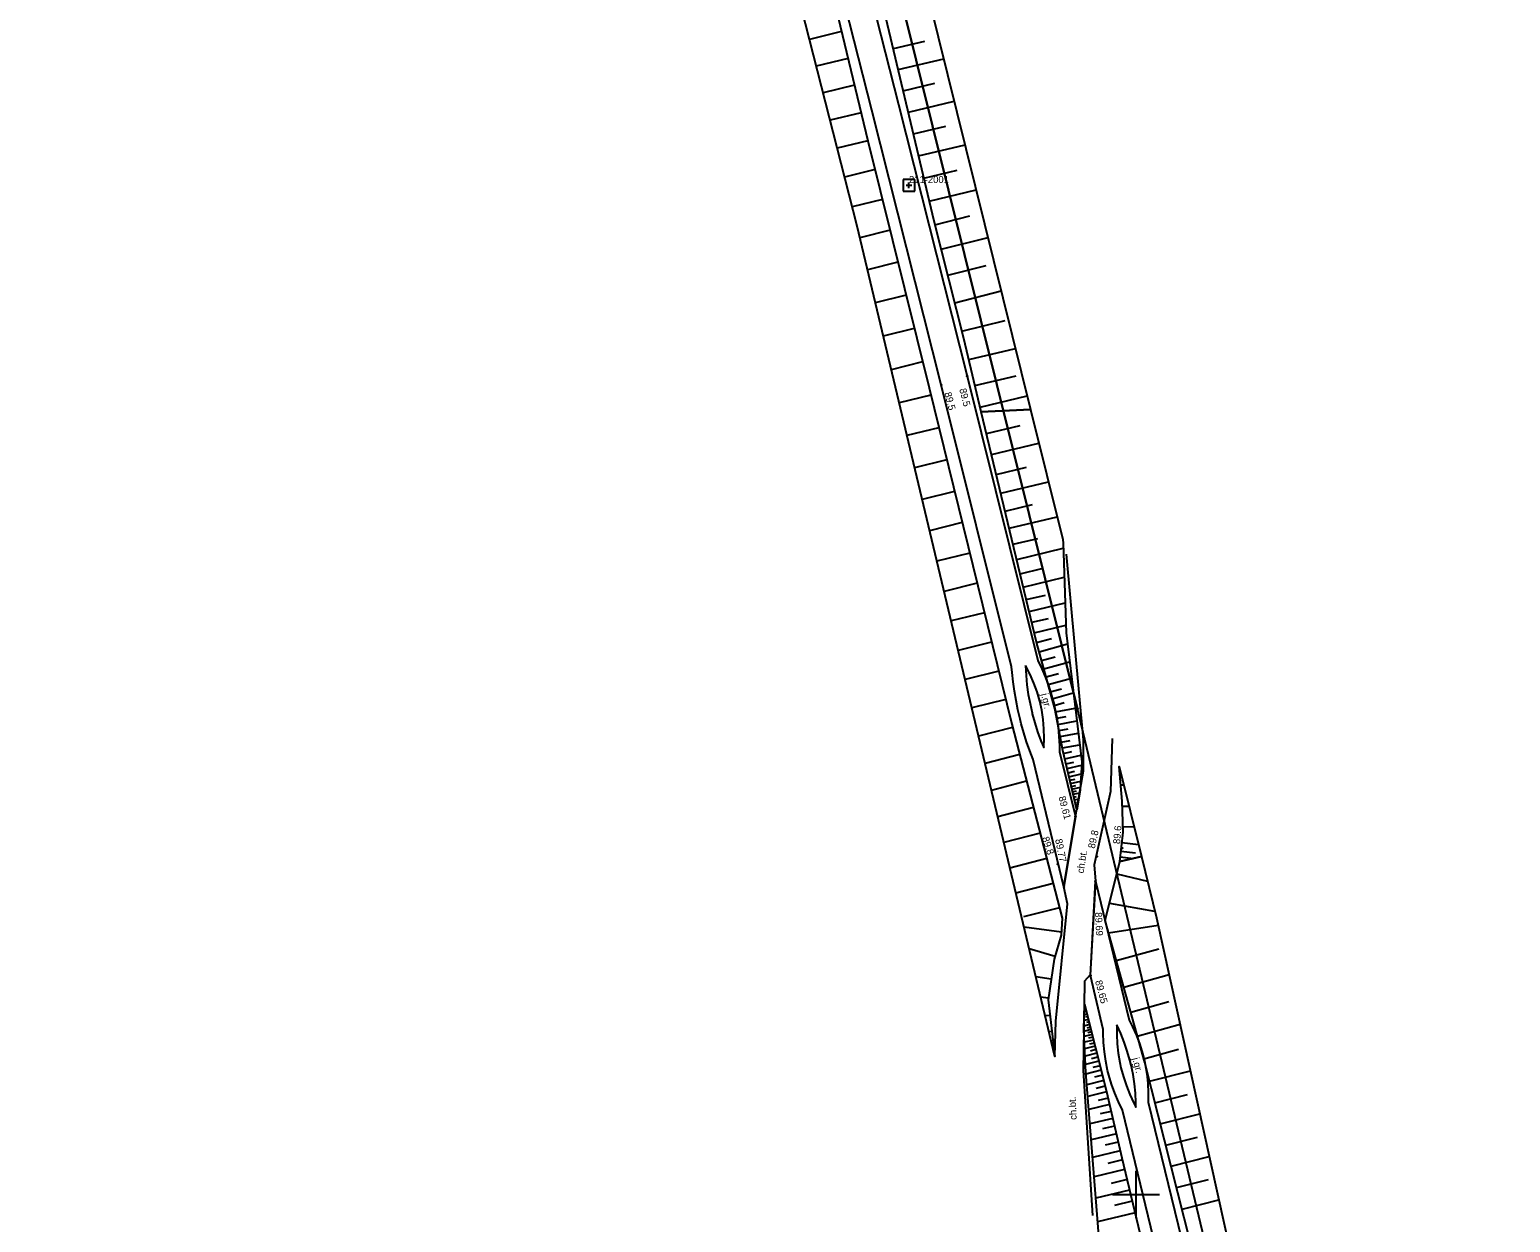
# Model space of a CAD drawing. Extents: x 7506075 to 7506993, y 5784375 to 5786367.
# Drawn here: x 7506732.7 to 7506889.7, y 5784747.1 to 5784873.4 of the extents above; entities that cross this region are included whole.
import ezdxf

# ---------------------------------------------------------------- set-up
doc = ezdxf.new("R2010")
doc.units = 0
for name, color, linetype in [('000 Inne (niezydentyfikowane)', 7, 'Continuous'), ('203-punkt graniczny', 7, 'Continuous'), ('216-obręb ewidencyjny', 7, 'Continuous'), ('218-kontur użytku gruntowego', 7, 'Continuous'), ('219-działka ewidencyjna', 7, 'Continuous'), ('chodnik', 7, 'Continuous'), ('chodnik-Atr17', 7, 'Continuous'), ('jezdnia', 7, 'Continuous'), ('jezdnia-Atr17', 7, 'Continuous'), ('pikieta naturalna', 7, 'Continuous'), ('pikieta naturalna-Atr2', 7, 'Continuous'), ('pikieta sztuczna', 7, 'Continuous'), ('pikieta sztuczna-Atr2', 7, 'Continuous'), ('skarpa nieumocniona', 7, 'Continuous'), ('skarpa umocniona', 7, 'Continuous'), ('Szczegółowa osnowa geodezyjna pozioma', 7, 'Continuous'), ('Szczegółowa osnowa geodezyjna pozioma-Atr103', 7, 'Continuous'), ('wał przeciwpowodziowy', 7, 'Continuous'), ('Wstawianie ramki sekcyjnej z opisem', 7, 'Continuous')]:
    doc.layers.add(name, color=color, linetype=linetype)

# ---------------------------------------------------------------- blocks, each defined once
blk = doc.blocks.new('PW01')
blk.add_circle((0, 0), 0.045)
blk = doc.blocks.new('203')
blk.add_circle((0, 0), 0.045)
blk = doc.blocks.new('OSSP')
for p, q in [((-0.626, 0.625), (-0.626, -0.625)), ((-0.626, 0.625), (-0.626, -0.625)), ((0.624, 0.625), (-0.626, 0.625)), ((0.624, 0.625), (-0.626, 0.625)), ((0.3, 0), (-0.3, 0)), ((0.3, 0), (-0.3, 0)), ((0, -0.3), (0, 0.3)), ((0, -0.3), (0, 0.3)), ((0.624, -0.625), (0.624, 0.625)), ((0.624, -0.625), (0.624, 0.625)), ((-0.626, -0.625), (0.624, -0.625)), ((-0.626, -0.625), (0.624, -0.625))]:
    blk.add_line(p, q)

msp = doc.modelspace()

# ---------------------------------------------------------------- linework, layer by layer
at = {"layer": '000 Inne (niezydentyfikowane)'}
for p, q in [((7506818.8, 5784873.2), (7506815.378, 5784872.379)), ((7506824.28, 5784871.4), (7506827.61, 5784872.19)), ((7506819.48, 5784870.36), (7506816.101, 5784869.55)), ((7506824.8, 5784869.18), (7506829.62, 5784870.323)), ((7506820.17, 5784867.51), (7506816.827, 5784866.705)), ((7506825.33, 5784866.94), (7506828.68, 5784867.73)), ((7506825.87, 5784864.67), (7506830.736, 5784865.818)), ((7506820.86, 5784864.61), (7506817.564, 5784863.819)), ((7506826.41, 5784862.37), (7506829.84, 5784863.18)), ((7506821.58, 5784861.64), (7506818.321, 5784860.853)), ((7506826.96, 5784860.04), (7506831.879, 5784861.208)), ((7506822.34, 5784858.58), (7506819.105, 5784857.781)), ((7506827.52, 5784857.68), (7506831.04, 5784858.51)), ((7506828.09, 5784855.25), (7506833.064, 5784856.426)), ((7506823.12, 5784855.42), (7506819.911, 5784854.624)), ((7506828.69, 5784852.74), (7506832.4, 5784853.68)), ((7506823.93, 5784852.15), (7506820.723, 5784851.359)), ((7506829.35, 5784850.14), (7506834.31, 5784851.398)), ((7506824.76, 5784848.78), (7506821.53, 5784847.974)), ((7506830.05, 5784847.39), (7506834.1, 5784848.41)), ((7506825.63, 5784845.28), (7506822.364, 5784844.473)), ((7506830.78, 5784844.48), (7506835.715, 5784845.73)), ((7506826.5, 5784841.75), (7506823.207, 5784840.935)), ((7506831.55, 5784841.45), (7506836.11, 5784842.6)), ((7506832.28, 5784838.45), (7506837.226, 5784839.632)), ((7506827.38, 5784838.2), (7506824.055, 5784837.377)), ((7506832.93, 5784835.7), (7506837.28, 5784836.74)), ((7506828.25, 5784834.69), (7506824.892, 5784833.863)), ((7506833.48, 5784833.41), (7506838.473, 5784834.601)), ((7506829.1, 5784831.23), (7506825.718, 5784830.397)), ((7506834.15, 5784830.61), (7506837.72, 5784831.47)), ((7506834.69, 5784828.4), (7506839.712, 5784829.604)), ((7506829.94, 5784827.82), (7506826.532, 5784826.98)), ((7506835.19, 5784826.29), (7506838.4, 5784827.06)), ((7506830.77, 5784824.47), (7506827.331, 5784823.626)), ((7506835.67, 5784824.29), (7506840.729, 5784825.501)), ((7506836.12, 5784822.39), (7506839.02, 5784823.09)), ((7506831.58, 5784821.18), (7506828.117, 5784820.327)), ((7506836.56, 5784820.59), (7506841.643, 5784821.812)), ((7506836.97, 5784818.89), (7506839.58, 5784819.51)), ((7506837.35, 5784817.27), (7506842.29, 5784818.46)), ((7506832.37, 5784817.95), (7506828.888, 5784817.091)), ((7506837.71, 5784815.76), (7506840.03, 5784816.32)), ((7506838.05, 5784814.35), (7506842.39, 5784815.39)), ((7506833.16, 5784814.76), (7506829.649, 5784813.899)), ((7506838.37, 5784813.02), (7506840.4, 5784813.51)), ((7506838.67, 5784811.78), (7506842.48, 5784812.69)), ((7506833.93, 5784811.63), (7506830.397, 5784810.76)), ((7506838.95, 5784810.62), (7506840.73, 5784811.04)), ((7506839.21, 5784809.52), (7506842.55, 5784810.32)), ((7506839.46, 5784808.48), (7506841.03, 5784808.91)), ((7506834.69, 5784808.52), (7506831.139, 5784807.644)), ((7506839.73, 5784807.5), (7506842.72, 5784808.33)), ((7506835.45, 5784805.45), (7506831.872, 5784804.569)), ((7506839.99, 5784806.57), (7506841.42, 5784806.97)), ((7506840.24, 5784805.68), (7506842.95, 5784806.43)), ((7506840.48, 5784804.83), (7506841.77, 5784805.19)), ((7506840.7, 5784804.03), (7506843.16, 5784804.71)), ((7506836.19, 5784802.44), (7506832.592, 5784801.547)), ((7506840.91, 5784803.26), (7506842.09, 5784803.58)), ((7506841.12, 5784802.52), (7506843.35, 5784803.14)), ((7506841.31, 5784801.82), (7506842.38, 5784802.12)), ((7506841.47, 5784801.14), (7506843.55, 5784801.53)), ((7506836.92, 5784799.49), (7506833.306, 5784798.55)), ((7506841.6, 5784800.47), (7506842.61, 5784800.66)), ((7506841.72, 5784799.81), (7506843.71, 5784800.18)), ((7506841.84, 5784799.16), (7506842.82, 5784799.35)), ((7506841.96, 5784798.53), (7506843.87, 5784798.89)), ((7506842.08, 5784797.91), (7506843.01, 5784798.09)), ((7506842.19, 5784797.31), (7506844.02, 5784797.65)), ((7506837.67, 5784796.61), (7506833.995, 5784795.659)), ((7506842.32, 5784796.73), (7506843.2, 5784796.93)), ((7506842.45, 5784796.16), (7506844.15, 5784796.56)), ((7506842.57, 5784795.63), (7506843.39, 5784795.82)), ((7506842.69, 5784795.13), (7506844.22, 5784795.49)), ((7506842.79, 5784794.68), (7506843.49, 5784794.84)), ((7506842.89, 5784794.26), (7506844.17, 5784794.56)), ((7506838.4, 5784793.78), (7506834.672, 5784792.817)), ((7506842.98, 5784793.88), (7506843.56, 5784794.02)), ((7506843.06, 5784793.53), (7506844.13, 5784793.78)), ((7506843.13, 5784793.22), (7506843.62, 5784793.33)), ((7506843.2, 5784792.93), (7506844.1, 5784793.14)), ((7506848.37, 5784793.39), (7506848.681, 5784793.416)), ((7506843.26, 5784792.66), (7506843.67, 5784792.75)), ((7506843.32, 5784792.41), (7506844.03, 5784792.57)), ((7506843.39, 5784792.11), (7506843.68, 5784792.18)), ((7506843.46, 5784791.82), (7506843.92, 5784791.92)), ((7506843.53, 5784791.52), (7506843.69, 5784791.56)), ((7506839.12, 5784791.01), (7506835.337, 5784790.025)), ((7506843.6, 5784791.23), (7506843.8, 5784791.28)), ((7506848.53, 5784791.13), (7506849.241, 5784791.156)), ((7506839.83, 5784788.28), (7506835.991, 5784787.282)), ((7506848.61, 5784788.94), (7506849.78, 5784788.983)), ((7506848.5, 5784787.29), (7506850.25, 5784787.087)), ((7506840.53, 5784785.6), (7506836.633, 5784784.588)), ((7506848.33, 5784785.77), (7506849.73, 5784785.61)), ((7506848.4, 5784786.37), (7506849.94, 5784786.19)), ((7506847.95, 5784783.99), (7506851.218, 5784783.18)), ((7506841.21, 5784782.96), (7506837.264, 5784781.939)), ((7506841.88, 5784780.37), (7506838.07, 5784779.43)), ((7506847.17, 5784780.85), (7506851.97, 5784780.01)), ((7506842.09, 5784777.78), (7506838.129, 5784778.309)), ((7506847.08, 5784777.74), (7506852.352, 5784778.519)), ((7506841.41, 5784775.22), (7506838.675, 5784776.015)), ((7506847.9, 5784774.78), (7506852.42, 5784776.04)), ((7506841, 5784772.83), (7506839.375, 5784773.078)), ((7506848.69, 5784771.98), (7506853.5, 5784773.321)), ((7506840.69, 5784770.79), (7506839.891, 5784770.913)), ((7506844.67, 5784769.67), (7506844.53, 5784769.63)), ((7506844.74, 5784769.39), (7506844.63, 5784769.36)), ((7506849.43, 5784769.32), (7506853.48, 5784770.45)), ((7506840.87, 5784768.98), (7506840.366, 5784768.918)), ((7506845.09, 5784768), (7506844.46, 5784767.84)), ((7506844.95, 5784768.55), (7506844.49, 5784768.44)), ((7506844.81, 5784769.11), (7506844.51, 5784769.03)), ((7506844.88, 5784768.83), (7506844.69, 5784768.78)), ((7506845.02, 5784768.28), (7506844.75, 5784768.21)), ((7506850.13, 5784766.79), (7506854.664, 5784768.051)), ((7506841.08, 5784767.28), (7506840.766, 5784767.241)), ((7506845.22, 5784767.47), (7506844.46, 5784767.28)), ((7506845.35, 5784766.96), (7506844.49, 5784766.74)), ((7506845.5, 5784766.37), (7506844.52, 5784766.13)), ((7506845.16, 5784767.72), (7506844.81, 5784767.63)), ((7506845.28, 5784767.22), (7506844.88, 5784767.12)), ((7506845.42, 5784766.67), (7506844.96, 5784766.56)), ((7506841.28, 5784765.61), (7506841.158, 5784765.595)), ((7506845.66, 5784765.71), (7506844.55, 5784765.44)), ((7506845.85, 5784764.97), (7506844.59, 5784764.65)), ((7506845.58, 5784766.05), (7506845.06, 5784765.92)), ((7506845.75, 5784765.35), (7506845.16, 5784765.2)), ((7506850.81, 5784764.36), (7506854.49, 5784765.39)), ((7506846.06, 5784764.12), (7506844.64, 5784763.76)), ((7506846.3, 5784763.16), (7506844.69, 5784762.75)), ((7506845.95, 5784764.56), (7506845.28, 5784764.39)), ((7506846.18, 5784763.65), (7506845.42, 5784763.46)), ((7506851.42, 5784762.01), (7506855.754, 5784763.112)), ((7506846.58, 5784762.08), (7506844.78, 5784761.63)), ((7506846.44, 5784762.63), (7506845.59, 5784762.42)), ((7506846.88, 5784760.87), (7506844.88, 5784760.4)), ((7506846.72, 5784761.49), (7506845.78, 5784761.25)), ((7506847.03, 5784760.21), (7506845.98, 5784759.97)), ((7506852, 5784759.73), (7506855.45, 5784760.6)), ((7506847.19, 5784759.53), (7506844.99, 5784759.02)), ((7506847.36, 5784758.8), (7506846.2, 5784758.54)), ((7506852.57, 5784757.48), (7506856.763, 5784758.542)), ((7506847.53, 5784758.05), (7506845.11, 5784757.48)), ((7506847.72, 5784757.25), (7506846.45, 5784756.96)), ((7506847.91, 5784756.42), (7506845.24, 5784755.8)), ((7506848.11, 5784755.54), (7506846.71, 5784755.22)), ((7506853.14, 5784755.24), (7506856.5, 5784756.09)), ((7506848.33, 5784754.62), (7506845.39, 5784753.94)), ((7506848.55, 5784753.66), (7506847.01, 5784753.29)), ((7506853.71, 5784753), (7506857.76, 5784754.028)), ((7506848.79, 5784752.65), (7506845.55, 5784751.87)), ((7506849.05, 5784751.59), (7506847.35, 5784751.18)), ((7506854.28, 5784750.73), (7506857.66, 5784751.59)), ((7506849.32, 5784750.47), (7506845.73, 5784749.61)), ((7506849.6, 5784749.3), (7506847.71, 5784748.84)), ((7506854.87, 5784748.44), (7506858.775, 5784749.433)), ((7506849.89, 5784748.06), (7506845.93, 5784747.11))]:
    msp.add_line(p, q, dxfattribs=at)
at = {"layer": '216-obręb ewidencyjny'}
for points in [[(7506843.79, 5784801.45), (7506732.74, 5785247.89)], [(7506861.31, 5784728.22), (7506843.79, 5784801.45)]]:
    msp.add_lwpolyline(points, dxfattribs=at)
at = {"layer": '218-kontur użytku gruntowego'}
for points in [[(7506843.79, 5784801.45), (7506732.74, 5785247.89)], [(7506861.31, 5784728.22), (7506843.79, 5784801.45)]]:
    msp.add_lwpolyline(points, dxfattribs=at)
at = {"layer": '219-działka ewidencyjna'}
for points in [[(7506843.79, 5784801.45), (7506732.74, 5785247.89)], [(7506732.74, 5785247.89), (7506843.79, 5784801.45)], [(7506861.31, 5784728.22), (7506843.79, 5784801.45)], [(7506861.31, 5784728.22), (7506843.79, 5784801.45)]]:
    msp.add_lwpolyline(points, dxfattribs=at)
at = {"layer": 'chodnik'}
for points in [[(7506841.385, 5784764.642), (7506841.485, 5784768.377), (7506842.751, 5784780.803), (7506842.36, 5784782.6), (7506843.59, 5784790.05), (7506844.43, 5784794.88), (7506844.44, 5784798.17), (7506842.63, 5784817.829)], [(7506847.47, 5784798.301), (7506847.29, 5784792.68), (7506845.56, 5784784.92), (7506845.71, 5784783.21), (7506845.14, 5784773.273), (7506844.548, 5784772.592), (7506844.45, 5784767.49), (7506844.4, 5784763.13), (7506845.4, 5784747.793)]]:
    msp.add_lwpolyline(points, dxfattribs=at)
at = {"layer": 'jezdnia'}
for points in [[(7506817.25, 5784895.19), (7506824.81, 5784865.48), (7506832.09, 5784836.69), (7506839.6, 5784806.59), (7506840.03, 5784805.69), (7506840.41, 5784804.76), (7506840.76, 5784803.82), (7506841.05, 5784802.87), (7506841.31, 5784801.9), (7506841.4, 5784801.5), (7506841.59, 5784800.52), (7506841.73, 5784799.53), (7506841.83, 5784798.53), (7506841.88, 5784797.54), (7506841.89, 5784796.89), (7506843.59, 5784790.05), (7506842.36, 5784782.6), (7506842.36, 5784782.6), (7506839.08, 5784796.07), (7506838.73, 5784797.01), (7506838.4, 5784797.95), (7506838.1, 5784798.9), (7506837.83, 5784799.87), (7506837.7, 5784800.37), (7506837.47, 5784801.34), (7506837.28, 5784802.32), (7506837.11, 5784803.31), (7506836.97, 5784804.3), (7506836.86, 5784805.3), (7506836.81, 5784805.89), (7506829.36, 5784835.78), (7506821.98, 5784864.89), (7506814.49, 5784894.42)], [(7506855.64, 5784729.76), (7506848.57, 5784758.93), (7506848.13, 5784759.83), (7506847.74, 5784760.75), (7506847.4, 5784761.69), (7506847.11, 5784762.65), (7506846.99, 5784763.14), (7506846.79, 5784764.12), (7506846.65, 5784765.11), (7506846.56, 5784766.11), (7506846.53, 5784767.1), (7506846.53, 5784767.48), (7506845.16, 5784773.19), (7506845.71, 5784783.21), (7506849.27, 5784768.47), (7506849.63, 5784767.75), (7506850.04, 5784766.83), (7506850.39, 5784765.9), (7506850.68, 5784764.94), (7506850.92, 5784763.97), (7506850.96, 5784763.77), (7506851.13, 5784762.78), (7506851.25, 5784761.79), (7506851.3, 5784760.79), (7506851.3, 5784759.79), (7506858.35, 5784730.83)]]:
    msp.add_lwpolyline(points, dxfattribs=at)
for points in [[(7506838.27, 5784806.03), (7506838.35, 5784804.98), (7506838.44, 5784803.98), (7506838.58, 5784802.99), (7506838.76, 5784802.01), (7506838.98, 5784801.03), (7506839, 5784800.93), (7506839.26, 5784799.97), (7506839.57, 5784799.01), (7506839.91, 5784798.07), (7506840.21, 5784797.35), (7506840.26, 5784798.35), (7506840.23, 5784799.35), (7506840.15, 5784800.34), (7506840, 5784801.3), (7506839.79, 5784802.28), (7506839.51, 5784803.24), (7506839.17, 5784804.18), (7506838.76, 5784805.09)], [(7506847.95, 5784767.96), (7506847.95, 5784766.96), (7506848, 5784765.96), (7506848.11, 5784764.97), (7506848.28, 5784763.98), (7506848.4, 5784763.43), (7506848.66, 5784762.46), (7506848.97, 5784761.51), (7506849.34, 5784760.58), (7506849.76, 5784759.68), (7506849.98, 5784759.24), (7506849.98, 5784759.74), (7506849.93, 5784760.74), (7506849.83, 5784761.73), (7506849.68, 5784762.72), (7506849.48, 5784763.7), (7506849.35, 5784764.22), (7506849.07, 5784765.18), (7506848.75, 5784766.13), (7506848.37, 5784767.05)]]:
    msp.add_lwpolyline(points, close=True, dxfattribs=at)
at = {"layer": 'skarpa nieumocniona'}
msp.add_lwpolyline([(7506850.57, 5784785.8), (7506848.27, 5784785.27), (7506848.63, 5784788.4), (7506848.51, 5784791.68), (7506848.2, 5784795.34)], close=True, dxfattribs=at)
at = {"layer": 'skarpa umocniona'}
msp.add_lwpolyline([(7506814.16, 5784892.51), (7506821.58, 5784861.63), (7506828.06, 5784835.47), (7506836.83, 5784799.84), (7506842.17, 5784779.27), (7506842.07, 5784777.48), (7506841.32, 5784774.92), (7506840.67, 5784770.64), (7506841.37, 5784764.9), (7506841.39, 5784764.64), (7506820.43, 5784852.59), (7506777.49, 5785020.8)], dxfattribs=at)
msp.add_lwpolyline([(7506814.16, 5784892.51), (7506821.58, 5784861.63), (7506828.06, 5784835.47), (7506836.83, 5784799.84), (7506842.17, 5784779.27), (7506842.07, 5784777.48), (7506841.32, 5784774.92), (7506840.67, 5784770.64), (7506841.37, 5784764.9), (7506841.39, 5784764.64), (7506820.43, 5784852.59), (7506777.49, 5785020.8)], dxfattribs=at)
for points in [[(7506842.24, 5784819.41), (7506842.27, 5784818.99), (7506842.58, 5784809.49), (7506844.24, 5784795.83), (7506844.08, 5784792.85), (7506843.71, 5784790.74), (7506842.24, 5784797.05), (7506841.4, 5784801.5), (7506839.45, 5784808.53), (7506833.6, 5784832.92), (7506838.83, 5784833.15)], [(7506842.24, 5784819.41), (7506842.27, 5784818.99), (7506842.58, 5784809.49), (7506844.24, 5784795.83), (7506844.08, 5784792.85), (7506843.71, 5784790.74), (7506842.24, 5784797.05), (7506841.4, 5784801.5), (7506839.45, 5784808.53), (7506833.6, 5784832.92), (7506838.83, 5784833.15)], [(7506852.18, 5784779.3), (7506868.65, 5784704.71), (7506880.2, 5784658), (7506889.57, 5784624.57), (7506889.67, 5784619.16), (7506889.01, 5784613.23), (7506888.53, 5784611.18), (7506886.62, 5784618.3), (7506884.17, 5784629.55), (7506882.82, 5784635.93), (7506878.57, 5784651.6), (7506876.16, 5784660.02), (7506872.84, 5784673.6), (7506869.37, 5784689.41), (7506862.11, 5784719.93), (7506850.92, 5784763.97), (7506846.72, 5784779.03), (7506848.27, 5784785.27), (7506850.57, 5784785.8)], [(7506852.18, 5784779.3), (7506868.65, 5784704.71), (7506880.2, 5784658), (7506889.57, 5784624.57), (7506889.67, 5784619.16), (7506889.01, 5784613.23), (7506888.53, 5784611.18), (7506886.62, 5784618.3), (7506884.17, 5784629.55), (7506882.82, 5784635.93), (7506878.57, 5784651.6), (7506876.16, 5784660.02), (7506872.84, 5784673.6), (7506869.37, 5784689.41), (7506862.11, 5784719.93), (7506850.92, 5784763.97), (7506846.72, 5784779.03), (7506848.27, 5784785.27), (7506850.57, 5784785.8)], [(7506846.87, 5784760.9), (7506848.5, 5784753.88), (7506851.4, 5784741.77), (7506856.01, 5784722.5), (7506859.35, 5784709.08), (7506862.08, 5784697.31), (7506866.86, 5784677.84), (7506875.08, 5784646.66), (7506882.75, 5784615.2), (7506883.83, 5784608.06), (7506883.96, 5784604.28), (7506883.4, 5784600.35), (7506880.23, 5784597.29), (7506868.65, 5784643.89), (7506850.59, 5784726.01), (7506846.12, 5784744.79), (7506844.68, 5784762.93), (7506844.45, 5784767.49), (7506844.55, 5784770.15)], [(7506846.87, 5784760.9), (7506848.5, 5784753.88), (7506851.4, 5784741.77), (7506856.01, 5784722.5), (7506859.35, 5784709.08), (7506862.08, 5784697.31), (7506866.86, 5784677.84), (7506875.08, 5784646.66), (7506882.75, 5784615.2), (7506883.83, 5784608.06), (7506883.96, 5784604.28), (7506883.4, 5784600.35), (7506880.23, 5784597.29), (7506868.65, 5784643.89), (7506850.59, 5784726.01), (7506846.12, 5784744.79), (7506844.68, 5784762.93), (7506844.45, 5784767.49), (7506844.55, 5784770.15)]]:
    msp.add_lwpolyline(points, close=True, dxfattribs=at)
at = {"layer": 'wał przeciwpowodziowy'}
msp.add_lwpolyline([(7506824.16, 5784892.35), (7506838.83, 5784833.15), (7506833.6, 5784832.92), (7506831.74, 5784840.7), (7506828.6, 5784853.11), (7506822.36, 5784879.51)], dxfattribs=at)
msp.add_lwpolyline([(7506824.16, 5784892.35), (7506838.83, 5784833.15), (7506833.6, 5784832.92), (7506831.74, 5784840.7), (7506828.6, 5784853.11), (7506822.36, 5784879.51)], dxfattribs=at)
at = {"layer": 'Wstawianie ramki sekcyjnej z opisem'}
for points in [[(7506850, 5784747.5), (7506850, 5784752.5)], [(7506847.5, 5784750), (7506852.5, 5784750)]]:
    msp.add_lwpolyline(points, dxfattribs=at)

# ---------------------------------------------------------------- block references
at = {"layer": '203-punkt graniczny'}
msp.add_blockref('203', (7506843.79, 5784801.45), dxfattribs=at)
at = {"layer": 'pikieta naturalna'}
for p in [(7506829.36, 5784835.78), (7506832.09, 5784836.69), (7506848.54, 5784786.7), (7506845.84, 5784785.8), (7506841.72, 5784785)]:
    msp.add_blockref('PW01', p, dxfattribs=at)
at = {"layer": 'pikieta sztuczna'}
for p in [(7506843.59, 5784790.05), (7506842.36, 5784782.6), (7506845.71, 5784783.21), (7506845.16, 5784773.19)]:
    msp.add_blockref('PW01', p, dxfattribs=at)
at = {"layer": 'Szczegółowa osnowa geodezyjna pozioma'}
msp.add_blockref('OSSP', (7506825.93, 5784856.91), dxfattribs=at)

# ---------------------------------------------------------------- texts
at = {"layer": 'chodnik-Atr17'}
for rotation, p in [(81.1906, (7506844.445, 5784783.993)), (92.569, (7506843.708, 5784757.927))]:
    msp.add_text('ch.bt.', height=0.75, rotation=rotation, dxfattribs=at).set_placement(p)
at = {"layer": 'jezdnia-Atr17'}
for rotation, p in [(283.387, (7506839.928, 5784803.011)), (283.387, (7506839.928, 5784803.011)), (283.387, (7506839.928, 5784803.011)), (284.87, (7506849.587, 5784764.409)), (284.87, (7506849.587, 5784764.409)), (284.87, (7506849.587, 5784764.409))]:
    msp.add_text('j.gr.', height=0.75, rotation=rotation, dxfattribs=at).set_placement(p)
at = {"layer": 'pikieta naturalna-Atr2'}
for s, rotation, p in [('89.5', 284.172, (7506831.261, 5784835.307)), ('89.5', 284.878, (7506829.674, 5784834.908)), ('89.8', 77.828, (7506845.624, 5784786.603)), ('89.6', 84.958, (7506848.3, 5784787.105)), ('89.8', 288.146, (7506840.02, 5784787.774))]:
    msp.add_text(s, height=0.75, rotation=rotation, dxfattribs=at).set_placement(p)
at = {"layer": 'pikieta sztuczna-Atr2'}
for s, rotation, p in [('89.61', 284.564, (7506841.777, 5784792.105)), ('89.77', 281.384, (7506841.417, 5784787.607)), ('89.69', 272.952, (7506845.638, 5784779.891)), ('89.65', 284.824, (7506845.647, 5784772.595))]:
    msp.add_text(s, height=0.75, rotation=rotation, dxfattribs=at).set_placement(p)
at = {"layer": 'Szczegółowa osnowa geodezyjna pozioma-Atr103'}
msp.add_text('211-2001', height=0.75, dxfattribs=at).set_placement((7506825.93, 5784857.16))

doc.saveas('drawing.dxf')
